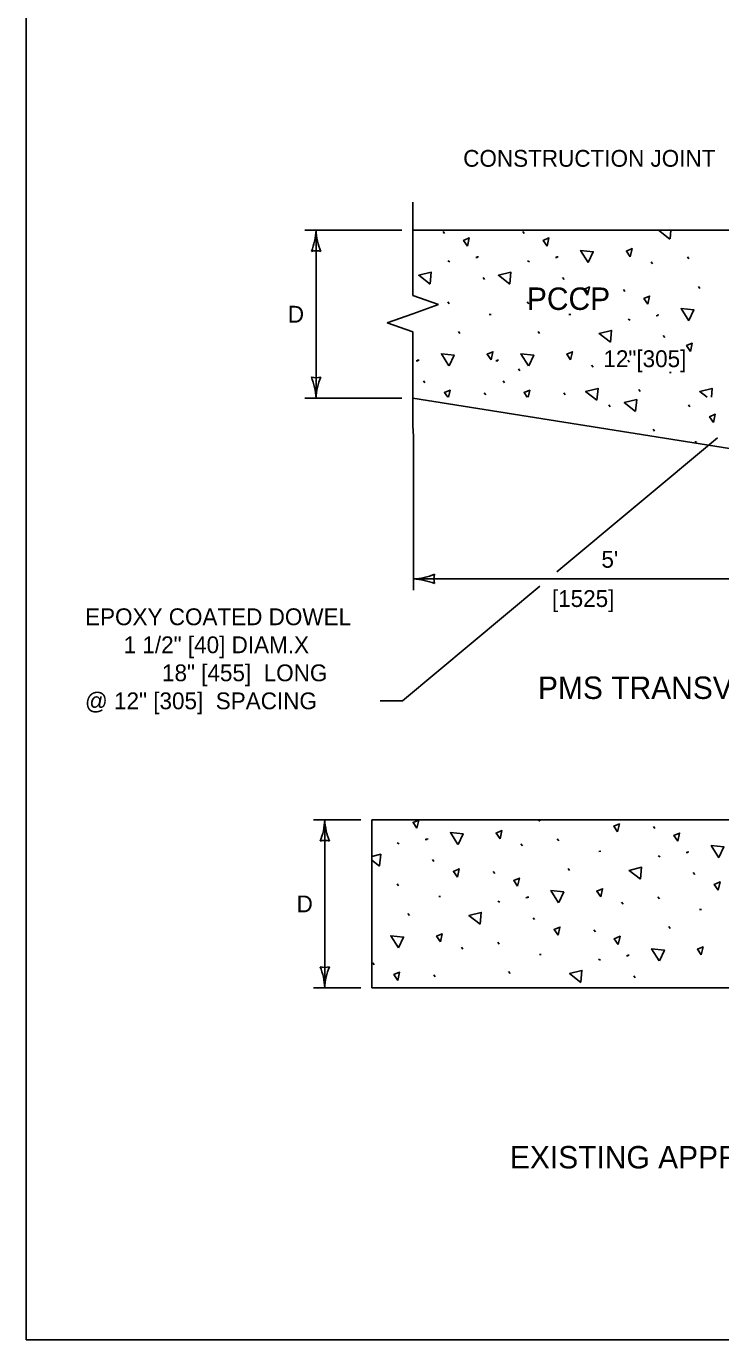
# Model space of a CAD drawing. Extents: x 49979.1 to 50021, y 49966.7 to 50011.4.
# Drawn here: x 49999.384 to 50001.863, y 49987.799 to 49992.485 of the extents above; entities that cross this region are included whole.
import ezdxf

# ---------------------------------------------------------------- set-up
doc = ezdxf.new("R2010")
doc.units = 0
for name, color, linetype in [('Level 1', 7, 'Continuous'), ('Level 13', 7, 'Continuous'), ('Level 2', 7, 'Continuous'), ('Level 3', 7, 'Continuous'), ('Level 6', 7, 'Continuous')]:
    doc.layers.add(name, color=color, linetype=linetype)

msp = doc.modelspace()

# ---------------------------------------------------------------- linework, layer by layer
at = {"layer": 'Level 1'}
for p, q in [((50005.5068, 49991.7578), (50000.7637, 49991.7578)), ((50005.5068, 49991.7578), (50000.7637, 49991.7578)), ((50000.7637, 49991.1578), (50002.5747, 49990.8713)), ((50002.1337, 49989.6538), (50000.6173, 49989.6538)), ((50000.6173, 49989.6538), (50000.6173, 49989.0538)), ((50000.6173, 49989.0538), (50003.6456, 49989.0538))]:
    msp.add_line(p, q, dxfattribs=at)
msp.add_lwpolyline([(49999.3835, 49998.9992), (50016.7501, 49998.9992), (50016.7501, 49987.7988), (49999.3835, 49987.7988)], close=True, dxfattribs=at)
at = {"layer": 'Level 13'}
for p, q in [((50000.8771, 49991.7459), (50000.8719, 49991.7529)), ((50001.1612, 49991.7459), (50001.1561, 49991.7529)), ((50001.4286, 49991.7576), (50001.4285, 49991.7578)), ((50000.8883, 49991.6479), (50000.8956, 49991.6446)), ((50000.9885, 49991.66), (50000.9949, 49991.6604)), ((50000.992, 49991.6621), (50000.9984, 49991.6625)), ((50001.1725, 49991.6479), (50001.1798, 49991.6446)), ((50001.2727, 49991.66), (50001.279, 49991.6604)), ((50001.2762, 49991.6621), (50001.2826, 49991.6625)), ((50001.6195, 49991.6371), (50001.6144, 49991.6442)), ((50001.7491, 49991.6556), (50001.744, 49991.6627)), ((50001.0193, 49991.5817), (50001.0141, 49991.5888)), ((50001.3035, 49991.5817), (50001.2983, 49991.5888)), ((50001.5205, 49991.5385), (50001.5153, 49991.5455)), ((50001.7878, 49991.5502), (50001.7827, 49991.5573)), ((50000.893, 49991.4946), (50000.8879, 49991.5017)), ((50001.1772, 49991.4946), (50001.172, 49991.5017)), ((50001.0365, 49991.4569), (50001.0429, 49991.4574)), ((50001.3206, 49991.4569), (50001.327, 49991.4574)), ((50001.5317, 49991.4405), (50001.5391, 49991.4372)), ((50001.6319, 49991.4526), (50001.6383, 49991.453)), ((50001.6354, 49991.4547), (50001.6418, 49991.4551)), ((50000.9317, 49991.3892), (50000.9266, 49991.3963)), ((50001.2159, 49991.3892), (50001.2108, 49991.3963)), ((50001.6627, 49991.3743), (50001.6576, 49991.3814)), ((50000.7758, 49991.2916), (50000.7822, 49991.292)), ((50000.7793, 49991.2937), (50000.7857, 49991.2941)), ((50001.06, 49991.2916), (50001.0664, 49991.292)), ((50001.0635, 49991.2937), (50001.0699, 49991.2941)), ((50001.1455, 49991.2562), (50001.1404, 49991.2633)), ((50001.4068, 49991.2688), (50001.4017, 49991.2758)), ((50001.5364, 49991.2872), (50001.5313, 49991.2943)), ((50001.6799, 49991.2495), (50001.6863, 49991.2499)), ((50000.8066, 49991.2133), (50000.8014, 49991.2204)), ((50001.0908, 49991.2133), (50001.0856, 49991.2204)), ((50001.0236, 49991.1701), (50001.0185, 49991.1771)), ((50001.3078, 49991.1701), (50001.3026, 49991.1771)), ((50001.5752, 49991.1818), (50001.57, 49991.1889)), ((50001.4685, 49991.1275), (50001.4633, 49991.1346)), ((50001.7527, 49991.1275), (50001.7475, 49991.1346)), ((50001.6264, 49991.0404), (50001.6212, 49991.0475)), ((50001.7698, 49991.0027), (50001.7762, 49991.0031)), ((50001.6277, 49989.6228), (50001.6225, 49989.6299)), ((50000.7077, 49989.5712), (50000.7151, 49989.568)), ((50000.8079, 49989.5834), (50000.8143, 49989.5838)), ((50000.8115, 49989.5854), (50000.8178, 49989.5858)), ((50001.1548, 49989.5605), (50001.1496, 49989.5676)), ((50001.2844, 49989.579), (50001.2792, 49989.5861)), ((50001.4278, 49989.5413), (50001.4342, 49989.5417)), ((50001.6389, 49989.5248), (50001.6463, 49989.5216)), ((50001.7391, 49989.5369), (50001.7455, 49989.5374)), ((50001.7426, 49989.539), (50001.749, 49989.5394)), ((50000.8387, 49989.5051), (50000.8336, 49989.5121)), ((50001.0558, 49989.4618), (50001.0506, 49989.4689)), ((50001.3231, 49989.4736), (50001.318, 49989.4807)), ((50000.7125, 49989.418), (50000.7073, 49989.4251)), ((50001.7699, 49989.4586), (50001.7648, 49989.4657)), ((50000.8559, 49989.3803), (50000.8623, 49989.3807)), ((50001.1672, 49989.376), (50001.1736, 49989.3764)), ((50001.1707, 49989.378), (50001.1771, 49989.3784)), ((50001.6436, 49989.3716), (50001.6385, 49989.3787)), ((50001.067, 49989.3638), (50001.0743, 49989.3606)), ((50001.514, 49989.3531), (50001.5089, 49989.3602)), ((50001.7871, 49989.3339), (50001.7935, 49989.3343)), ((50000.7512, 49989.3126), (50000.746, 49989.3197)), ((50001.198, 49989.2977), (50001.1928, 49989.3047)), ((50001.415, 49989.2544), (50001.4098, 49989.2615)), ((50001.6824, 49989.2662), (50001.6772, 49989.2732)), ((50000.9421, 49989.1921), (50000.9369, 49989.1992)), ((50001.0717, 49989.2106), (50001.0666, 49989.2177)), ((50000.626, 49989.1367), (50000.6209, 49989.1438)), ((50001.2151, 49989.1729), (50001.2215, 49989.1733)), ((50001.4262, 49989.1564), (50001.4336, 49989.1532)), ((50001.5264, 49989.1686), (50001.5328, 49989.169)), ((50001.5299, 49989.1706), (50001.5363, 49989.171)), ((50000.8431, 49989.0934), (50000.8379, 49989.1005)), ((50001.1104, 49989.1052), (50001.1053, 49989.1123)), ((50001.5572, 49989.0903), (50001.5521, 49989.0973)), ((50001.7693, 49989.0538), (50001.7691, 49989.0541))]:
    msp.add_line(p, q, dxfattribs=at)
for points in [[(50000.9587, 49991.7008), (50000.9448, 49991.7211), (50000.9652, 49991.7298), (50000.9587, 49991.7008)], [(50001.2429, 49991.7008), (50001.229, 49991.7211), (50001.2494, 49991.7298), (50001.2429, 49991.7008)], [(50001.6815, 49991.7261), (50001.641, 49991.7576), (50001.6417, 49991.7578)], [(50001.6844, 49991.7578), (50001.6816, 49991.727)], [(50001.3894, 49991.6418), (50001.3622, 49991.6852), (50001.4077, 49991.6805), (50001.3899, 49991.6426)], [(50001.5396, 49991.663), (50001.5257, 49991.6833), (50001.5461, 49991.692), (50001.5396, 49991.663)], [(50000.8254, 49991.5651), (50000.7849, 49991.5966), (50000.8293, 49991.6077), (50000.8255, 49991.566)], [(50001.1095, 49991.5651), (50001.0691, 49991.5966), (50001.1135, 49991.6077), (50001.1097, 49991.566)], [(50001.3873, 49991.5262), (50001.3734, 49991.5465), (50001.3938, 49991.5552), (50001.3873, 49991.5262)], [(50001.6021, 49991.4934), (50001.5882, 49991.5137), (50001.6086, 49991.5224), (50001.6021, 49991.4934)], [(50001.7487, 49991.4344), (50001.7214, 49991.4778), (50001.7669, 49991.4731), (50001.7491, 49991.4352)], [(50001.4688, 49991.3577), (50001.4284, 49991.3892), (50001.4727, 49991.4003), (50001.4689, 49991.3586)], [(50001.7547, 49991.3254), (50001.7408, 49991.3457), (50001.7612, 49991.3544), (50001.7547, 49991.3254)], [(50000.8926, 49991.2734), (50000.8653, 49991.3168), (50000.9108, 49991.3121), (50000.893, 49991.2742)], [(50001.0427, 49991.2946), (50001.0288, 49991.3149), (50001.0492, 49991.3237), (50001.0427, 49991.2946)], [(50001.1767, 49991.2734), (50001.1495, 49991.3168), (50001.195, 49991.3121), (50001.1772, 49991.2742)], [(50001.3269, 49991.2946), (50001.313, 49991.3149), (50001.3334, 49991.3237), (50001.3269, 49991.2946)], [(50000.8879, 49991.1613), (50000.8765, 49991.1781), (50000.8969, 49991.1868), (50000.8912, 49991.1613)], [(50001.1721, 49991.1613), (50001.1607, 49991.1781), (50001.1811, 49991.1868), (50001.1754, 49991.1613)], [(50001.4207, 49991.1506), (50001.3803, 49991.182), (50001.4246, 49991.1932), (50001.4209, 49991.1514)], [(50001.8139, 49991.1613), (50001.7876, 49991.1818), (50001.8319, 49991.1929), (50001.8291, 49991.1613)], [(50001.5588, 49991.1109), (50001.5183, 49991.1424), (50001.5627, 49991.1535), (50001.5589, 49991.1118)], [(50001.8365, 49991.0719), (50001.8226, 49991.0923), (50001.843, 49991.101), (50001.8365, 49991.0719)], [(50000.7782, 49989.6242), (50000.7643, 49989.6445), (50000.7847, 49989.6532), (50000.7782, 49989.6242)], [(50001.0748, 49989.5864), (50001.0609, 49989.6067), (50001.0813, 49989.6154), (50001.0748, 49989.5864)], [(50001.2167, 49989.6495), (50001.2112, 49989.6538)], [(50001.2172, 49989.6538), (50001.2169, 49989.6504)], [(50001.4945, 49989.6105), (50001.4806, 49989.6308), (50001.501, 49989.6395), (50001.4945, 49989.6105)], [(50000.9247, 49989.5652), (50000.8975, 49989.6086), (50000.9429, 49989.6039), (50000.9251, 49989.5659)], [(50001.7093, 49989.5777), (50001.6954, 49989.5981), (50001.7158, 49989.6068), (50001.7093, 49989.5777)], [(50000.6173, 49989.5232), (50000.6487, 49989.5311), (50000.645, 49989.4894)], [(50001.8559, 49989.5187), (50001.8286, 49989.5622), (50001.8741, 49989.5574), (50001.8563, 49989.5195)], [(50000.6448, 49989.4885), (50000.6173, 49989.5099)], [(50000.9225, 49989.4495), (50000.9086, 49989.4698), (50000.929, 49989.4786), (50000.9225, 49989.4495)], [(50001.576, 49989.4421), (50001.5356, 49989.4736), (50001.5799, 49989.4847), (50001.5761, 49989.4429)], [(50001.1374, 49989.4167), (50001.1235, 49989.4371), (50001.1439, 49989.4458), (50001.1374, 49989.4167)], [(50001.8537, 49989.4031), (50001.8398, 49989.4234), (50001.8602, 49989.4321), (50001.8537, 49989.4031)], [(50001.2839, 49989.3578), (50001.2567, 49989.4012), (50001.3022, 49989.3965), (50001.2844, 49989.3585)], [(50001.4341, 49989.379), (50001.4202, 49989.3993), (50001.4406, 49989.408), (50001.4341, 49989.379)], [(50001.0041, 49989.2811), (50000.9636, 49989.3126), (50001.008, 49989.3237), (50001.0042, 49989.282)], [(50000.712, 49989.1968), (50000.6848, 49989.2402), (50000.7302, 49989.2355), (50000.7125, 49989.1976)], [(50000.8621, 49989.218), (50000.8482, 49989.2383), (50000.8687, 49989.247), (50000.8621, 49989.218)], [(50001.2818, 49989.2421), (50001.2679, 49989.2624), (50001.2883, 49989.2712), (50001.2818, 49989.2421)], [(50001.4966, 49989.2093), (50001.4827, 49989.2297), (50001.5031, 49989.2384), (50001.4966, 49989.2093)], [(50001.6432, 49989.1504), (50001.6159, 49989.1938), (50001.6614, 49989.1891), (50001.6436, 49989.1511)], [(50001.7933, 49989.1716), (50001.7794, 49989.1919), (50001.7998, 49989.2006), (50001.7933, 49989.1716)], [(50000.7098, 49989.0811), (50000.6959, 49989.1015), (50000.7164, 49989.1102), (50000.7098, 49989.0811)], [(50001.3633, 49989.0737), (50001.3229, 49989.1052), (50001.3672, 49989.1163), (50001.3635, 49989.0746)]]:
    msp.add_lwpolyline(points, dxfattribs=at)
at = {"layer": 'Level 3'}
for p, q in [((50000.7237, 49991.7578), (50000.378, 49991.7578)), ((50000.418, 49991.1578), (50000.418, 49991.7578)), ((50000.7237, 49991.1578), (50000.378, 49991.1578)), ((50000.7637, 49991.0613), (50000.7653, 49991.0214)), ((50000.7653, 49991.0214), (50000.7653, 49990.4733)), ((50001.8513, 49991.0173), (50001.2781, 49990.5389)), ((50000.7653, 49990.5133), (50002.1204, 49990.5133)), ((50001.2168, 49990.4877), (50000.7263, 49990.0783)), ((50000.7653, 49990.4733), (50000.7653, 49990.4733)), ((50000.6463, 49990.0783), (50000.7263, 49990.0783)), ((50000.5773, 49989.6538), (50000.4092, 49989.6538)), ((50000.4492, 49989.0538), (50000.4492, 49989.6538)), ((50000.5773, 49989.0538), (50000.4092, 49989.0538))]:
    msp.add_line(p, q, dxfattribs=at)
for centre, radius, start, end in [((50000.1959, 49991.7669), 0.2223, 337.456, 357.6395), ((50000.6507, 49991.7693), 0.233, 182.8273, 202.0772), ((50000.418, 49991.6295), 0.0548, 72.1388, 107.8612), ((50000.418, 49991.286), 0.0548, 252.1388, 287.8612), ((50000.1853, 49991.1463), 0.233, 2.8273, 22.0772), ((50000.6402, 49991.1486), 0.2223, 157.456, 177.6395), ((50000.7538, 49990.746), 0.233, 272.8273, 292.0772), ((50000.7562, 49990.2912), 0.2223, 67.456, 87.6395), ((50000.8935, 49990.5133), 0.0548, 162.1388, 197.8612), ((50000.2271, 49989.6629), 0.2223, 337.456, 357.6395), ((50000.6819, 49989.6653), 0.233, 182.8273, 202.0772), ((50000.4492, 49989.5256), 0.0548, 72.1388, 107.8612), ((50000.4492, 49989.182), 0.0548, 252.1388, 287.8612), ((50000.2165, 49989.0423), 0.233, 2.8273, 22.0772), ((50000.6713, 49989.0446), 0.2223, 157.456, 177.6395)]:
    msp.add_arc(centre, radius, start, end, dxfattribs=at)
at = {"layer": 'Level 6'}
for p, q in [((50000.7637, 49991.8578), (50000.7637, 49991.5244)), ((50000.8551, 49991.492), (50000.7637, 49991.5244)), ((50000.8551, 49991.492), (50000.7637, 49991.4596)), ((50000.7637, 49991.4596), (50000.6723, 49991.4272)), ((50000.7637, 49991.3948), (50000.6723, 49991.4272)), ((50000.7637, 49991.3948), (50000.7637, 49991.0613))]:
    msp.add_line(p, q, dxfattribs=at)

# ---------------------------------------------------------------- texts
at = {"layer": 'Level 2'}
for s, height, p in [('CONSTRUCTION JOINT', 0.06, (50000.9433, 49991.984)), ('PCCP', 0.08, (50001.1707, 49991.4732)), ('EPOXY COATED DOWEL', 0.06, (49999.5934, 49990.3483)), (' 1 1/2" [40] DIAM.X', 0.06, (49999.7089, 49990.2483)), (' 18" [455]  LONG', 0.06, (49999.8458, 49990.1483)), ('PMS TRANSVERSE TRANSITION DETAIL', 0.08, (50001.2102, 49990.0851)), ('@ 12" [305]  SPACING', 0.06, (49999.5931, 49990.0483)), ('EXISTING APPROACH SLAB TRANSITION DETAIL', 0.08, (50001.11, 49988.41))]:
    msp.add_text(s, height=height, dxfattribs=at).set_placement(p)
for s, rotation, p in [('D', 360, (50000.3173, 49991.4278)), ('12"[305]', 360, (50001.4438, 49991.2691)), ("5'", 0, (50001.4367, 49990.5533)), ('[1525]', 0, (50001.26, 49990.4133)), ('D', 360, (50000.3485, 49989.3238))]:
    msp.add_text(s, height=0.06, rotation=rotation, dxfattribs=at).set_placement(p)

doc.saveas('drawing.dxf')
